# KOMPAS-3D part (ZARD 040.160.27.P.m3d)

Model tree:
1. Плоскость XY
2. Плоскость ZX
3. Плоскость ZY
4. Ось X
5. Ось Y
6. Ось Z
7. Начало координат
8. Булева операция:1
9. Булева операция:2
10. Булева операция:3
11. Булева операция:4
